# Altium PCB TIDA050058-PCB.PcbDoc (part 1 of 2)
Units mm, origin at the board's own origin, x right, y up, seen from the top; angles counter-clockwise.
Board outline 100 x 60.38 mm, 2 copper layers (Top Layer, Bottom Layer), stack 1.575 mm thick; 72 components, 26 nets, 132 pads, 53 vias.
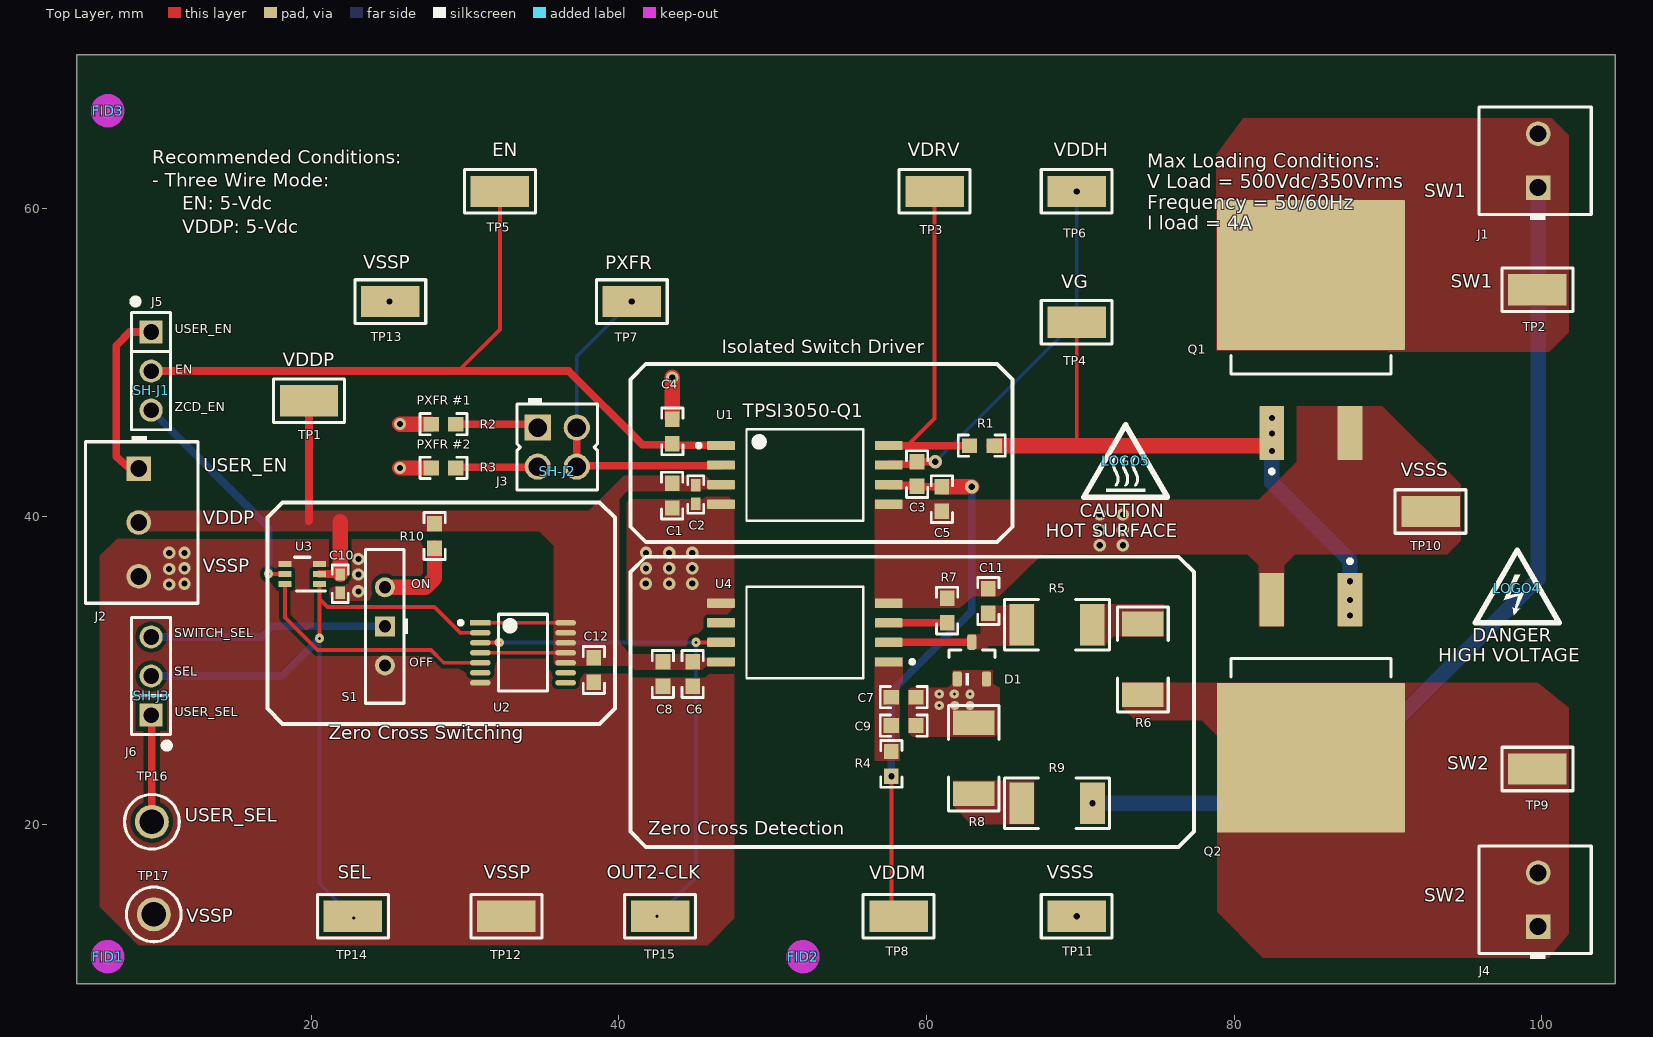
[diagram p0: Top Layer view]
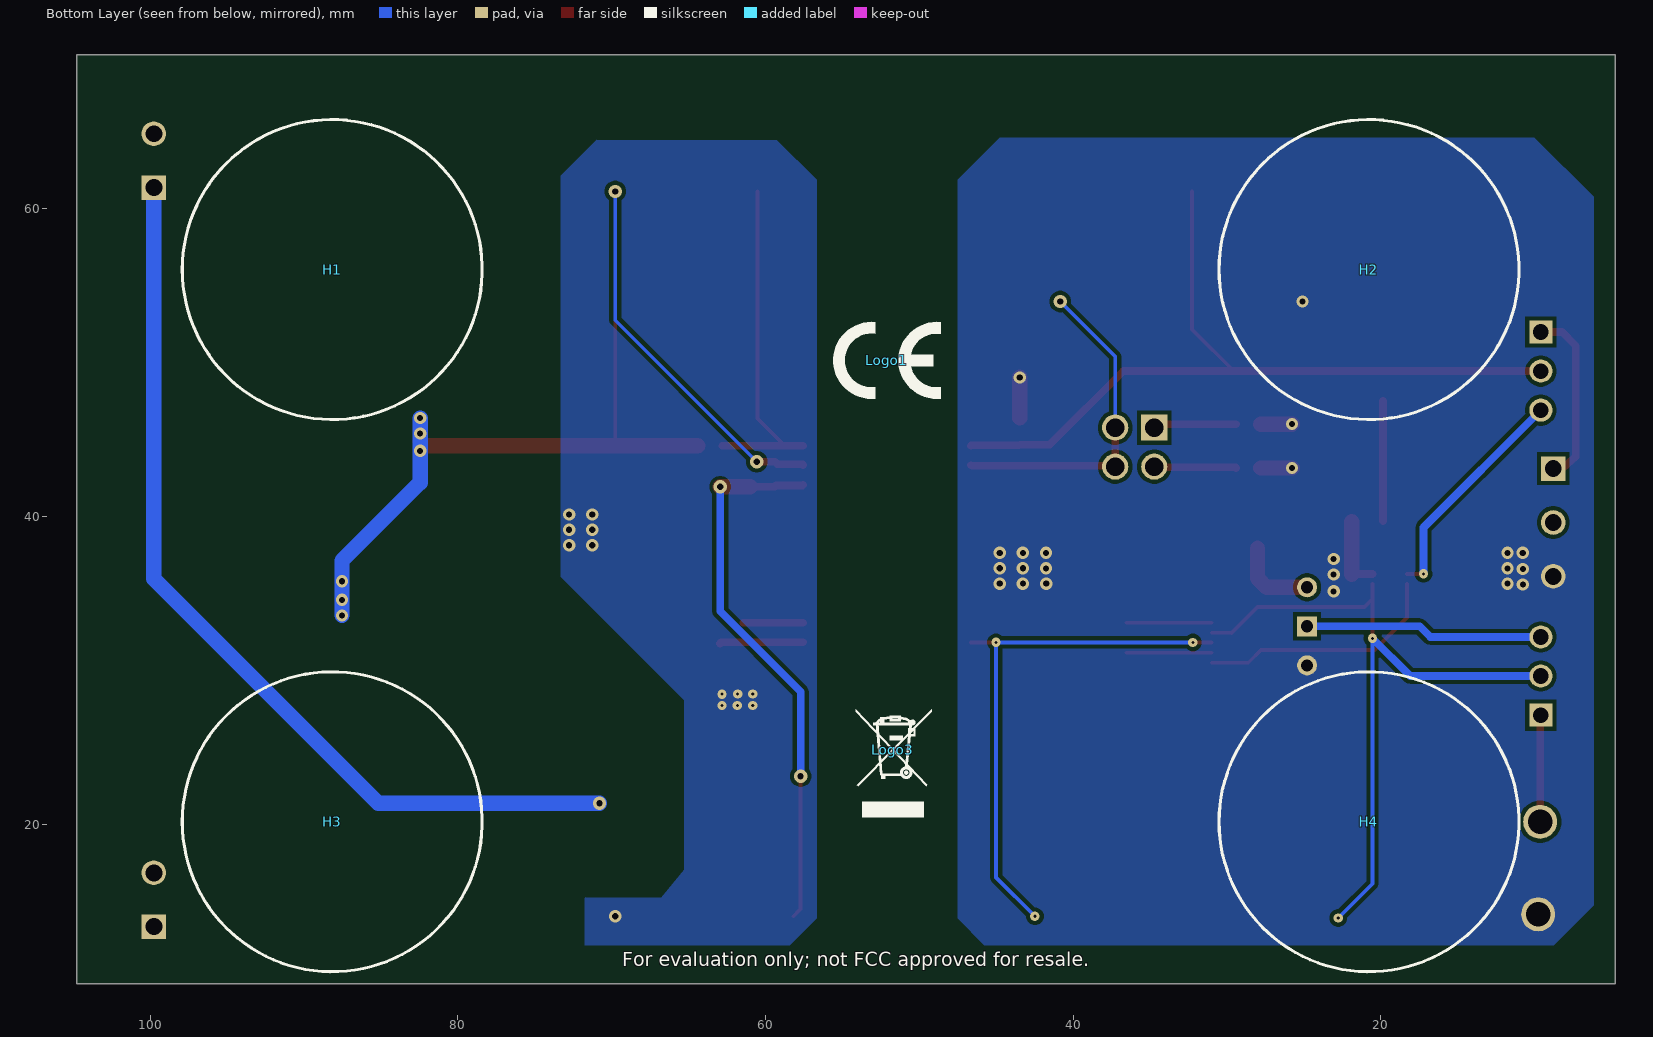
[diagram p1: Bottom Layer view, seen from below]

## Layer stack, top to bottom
Top Solder: solder mask 0.0102, Solder Resist, Dk 3.5
Top Layer: signal copper 0.0356
Dielectric1: core 1.5037, FR-4 High Tg, Dk 4.8
Bottom Layer: signal copper 0.0356
Bottom Solder: solder mask 0.0102, Solder Resist, Dk 3.5

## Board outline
4.775,9.625 104.775,9.625 104.775,70 4.775,70

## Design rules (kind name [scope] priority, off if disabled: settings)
AcuteAngle [All] p1: minimum=4.50000000000000E+0001 checktracksonly=FALSE
AssemblyTestPointUsage [All] p1: valid=2
BoardOutlineClearance BoardOutlineClearance_MountingHoles [OnCopper and InComponentClass('Mounting Holes')] p1: gap=1 ignorepadtopadclearanceinfootprint=FALSE
BoardOutlineClearance BoardOutlineClearance_Poly [OnCopper and IsPoly] p2: gap=0.635 ignorepadtopadclearanceinfootprint=FALSE
BoardOutlineClearance [OnCopper and Not InComponentClass('Logo') and not InComponentClass('FiducialMark') and not InRegion(1000,500,4000,800) and not InPoly] p3: gap=1.016 ignorepadtopadclearanceinfootprint=FALSE
Clearance Clearance_Keepouts [((IsTrack Or IsArc) And Not InPoly) And IsFree and IsKeepOut vs ((IsTrack Or IsArc) And Not InPoly) And IsFree and IsKeepOut] p1: gap=0 ignorepadtopadclearanceinfootprint=FALSE
Clearance Clearance_Poly [InPolygon] p2: gap=0.254 ignorepadtopadclearanceinfootprint=TRUE except(0.5: Fill-Fill Fill-Poly Fill-Region Poly-Poly Poly-Region Region-Region)
Clearance Clearance_FiducialMark [IsKeepOut and InComponentClass('FiducialMark') vs IsPad and InComponentClass('FiducialMark')] p3: gap=0 ignorepadtopadclearanceinfootprint=FALSE
Clearance [All] p4: gap=0.2 ignorepadtopadclearanceinfootprint=TRUE
ComponentClearance ComponentClearance_MountingHoles_FiducialMarks [InComponentClass('Mounting Holes') vs InComponentClass('FiducialMark')] p1: gap=1.27 collisioncheckmode=3 verticalgap=0.254 showdistances=FALSE
ComponentClearance ComponentClearance_Shunt [InComponentClass('Header') vs InComponentClass('Shunt')] p2: gap=0 collisioncheckmode=3 verticalgap=0 showdistances=FALSE
ComponentClearance ComponentClearance_Logo [InComponentClass('Logo')] p3: gap=0.762 collisioncheckmode=3 verticalgap=0.254 showdistances=FALSE
ComponentClearance ComponentClearance_ScrewToNut [(HasFootprint('NY PMS 440 0025 PH')) vs (HasFootprint('Keystone_1902C'))] p4: gap=0.127 collisioncheckmode=3 verticalgap=0.254 showdistances=FALSE
ComponentClearance ComponentClearance_MountingHoles [InComponentClass('Mounting Holes')] p5: gap=2.54 collisioncheckmode=3 verticalgap=2540 showdistances=FALSE
ComponentClearance ComponentClearance_SmallPassives [HasFootprint('0201*') or HasFootprint('0402*') or HasFootprint('0508') or HasFootprint('0603*') or HasFootprint('0612') or HasFootprint('0805*') or HasFootprint('0815*') or HasFootprint('0830*') or HasFootprint('1206*') or HasFootprint('1210*') or HasFootprint('1808*') or HasFootprint('1812*') or HasFootprint('1825*') or HasFootprint('2010*') or HasFootprint('2220*') or HasFootprint('2225*') or HasFootprint('2512*') or HasFootprint('2728*') or HasFootprint('3518*') vs HasFootprint('0201*') or HasFootprint('0402*') or HasFootprint('0508') or HasFootprint('0603*') or HasFootprint('0612') or HasFootprint('0805*') or HasFootprint('0815*') or HasFootprint('0830*') or HasFootprint('1206*') or HasFootprint('1210*') or HasFootprint('1808*') or HasFootprint('1812*') or HasFootprint('1825*') or HasFootprint('2010*') or HasFootprint('2220*') or HasFootprint('2225*') or HasFootprint('2512*') or HasFootprint('2728*') or HasFootprint('3518*')] p6: gap=0.38 collisioncheckmode=3 verticalgap=0.254 showdistances=FALSE
ComponentClearance ComponentClearance_THtoSMT [IsThruComponent vs IsSMTComponent] p7: gap=0.762 collisioncheckmode=3 verticalgap=0.762 showdistances=FALSE
ComponentClearance ComponentClearance_THtoTH [IsThruComponent vs IsThruComponent] p8: gap=0.508 collisioncheckmode=3 verticalgap=0.762 showdistances=FALSE
ComponentClearance [All] p9: gap=0.508 collisioncheckmode=3 verticalgap=0.254 showdistances=FALSE
DiffPairsRouting [All] p1: maxlimit=2.54 minlimit=0.254 mostfreqgap=0.254 toplayer_minwidth=0.381 toplayer_maxwidth=0.381 toplayer_prefwidth=0.381 bottomlayer_minwidth=0.381 bottomlayer_maxwidth=0.381 bottomlayer_prefwidth=0.381 maxuncoupledlength=25.4
FabricationTestPointUsage TestPointUsage [All] p1: valid=2 allowmultiple=FALSE
FabricationTestpoint Testpoint [All] p1: side=3 testpointundercomponent=TRUE minsize=1.016 maxsize=2.54 preferedsize=1.524 minholesize=0 maxholesize=1.016 preferedholesize=0.813 testpointgrid=0.025 allowsidetop=TRUE allowsidebottom=TRUE usegrid=TRUE gridtolerance=0
FanoutControl Fanout_LCC [IsLCC] p1: bgadir=Out bgaviamode=Centered fanoutstyle=Auto fanoutdirection=Alternating viagrid=0.025 // Fanout_LCC (Default Rule)
FanoutControl Fanout_BGA [IsBGA] p2: bgadir=Out bgaviamode=Centered fanoutstyle=Auto fanoutdirection=Alternating viagrid=0.025 // Fanout_BGA (Default Rule)
FanoutControl Fanout_Default [All] p4: bgadir=Out bgaviamode=Centered fanoutstyle=Auto fanoutdirection=Alternating viagrid=0.025 // Fanout_Default (Default Rule)
FanoutControl Fanout_Small [(CompPinCount < 5)] p5: bgadir=Out bgaviamode=Centered fanoutstyle=Auto fanoutdirection=OutThenIn viagrid=0.025 // Fanout_Small (Default Rule)
HoleSize [All] p1: absolutevalues=TRUE maxlimit=6.375 minlimit=0.2 maxpercent=80.000 minpercent=20.000
MinimumAnnularRing MinimumAnnularRing_ThermalPadVias [IsVia and InAnyComponent] p1: minimumring=0.15
MinimumAnnularRing [All] p2: minimumring=0.2
MinimumSolderMaskSliver MinimumSolderMaskSliver_Logo [InComponentClass('Logo') vs InComponentClass('Logo')] p1: minsoldermaskwidth=0.018
MinimumSolderMaskSliver [All] p2: minsoldermaskwidth=0.1
PlaneClearance [All] p1: clearance=0.5
PlaneConnect [All] p1: planeconnectstyle=Direct reliefexpansion=0.254 reliefentries=4 reliefconductorwidth=0.254 reliefairgap=0.254
PolygonConnect [All] p1: connectstyle=Direct reliefconductorwidth=0.254 reliefentries=4 polygonreliefangle="90 Angle" airgapwidth=0.254
RoutingVias ThermalPadVias [IsVia and InAnyComponent] p1: holewidth=0.4 width=0.8 viastyle="Through Hole" minholewidth=0.2 minwidth=0.5 maxholewidth=1 maxwidth=1.6
RoutingVias [All] p2: holewidth=0.406 width=0.864 viastyle="Through Hole" minholewidth=0.2 minwidth=0.61 maxholewidth=1.016 maxwidth=1.651
SilkToBoardRegionClearance [Not ((IsComment or IsDesignator) And (Hide <> 'False')) and not InRegion(1000,500,4000,800)] p1:
SilkToSilkClearance SilkToSilkClearance_Pb-FreeLogo [(HasFootprint('Pb-Free_Overlay_Medium') OR HasFootprint('Pb-Free_Overlay_Small')) vs (HasFootprint('Pb-Free_Overlay_Medium') OR HasFootprint('Pb-Free_Overlay_Small'))] p1: silktosilkclearance=0
SilkToSilkClearance [All] p2: silktosilkclearance=0.1
SilkToSolderMaskClearance SilkToComponentPadClearance [(IsPad or IsFill or IsRegion) and InAnycomponent] p1: minsilkscreentomaskgap=0.127 clearancetoexposedcopper=TRUE
SilkToSolderMaskClearance "Silk to Solder Mask Opening" [All] p2: minsilkscreentomaskgap=0.1 clearancetoexposedcopper=FALSE
SolderMaskExpansion [All] p1: expansion=0.05 istentingtop=FALSE
UnRoutedNet [All] p1: checkbadconnections=TRUE
Width [All] p1: maxlimit=1 minlimit=0.25 preferedwidth=0.5 minimp=50.000000 maximp=50.000000 favimp=50.000000 checkconnectedcopper=TRUE
13 further rules are at their usual default settings.

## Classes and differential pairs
component class Shunt: SH-J1 SH-J2 SH-J3
component class Header: J3 J5 J6
component class TIDA050058-Hardware: FID1 FID2 FID3 H1 H2 H3 H4 Logo1 Logo2 LOGO4 ZZ1 ZZ2 ZZ3 ZZ4
component class FiducialMark: FID1 FID2 FID3
component class AssemblyNote: ZZ1 ZZ2 ZZ3 ZZ4

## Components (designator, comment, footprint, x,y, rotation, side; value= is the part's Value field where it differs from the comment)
C1 "GRM188R71E224KA88D" 0603 43.476,41.345 r270 top value=0.22uF
C2 "GRM155R71E104KE14D" 0402 45.001,41.42 r270 top value=0.1uF
C3 "UMK107AB7105KA-T" 0603 59.391,42.745 r270 top value=1uF
C4 "C0603C102J5RACAUTO" 0603 43.49,45.52 r90 top value=1000pF
C5 "UMK107AB7105KA-T" 0603 61.007,41.12 r270 top value=1uF
C6 "GCM188R71E104KA57D" 0603 44.8,29.75 r270 top value=0.1uF
C7 "GCM188R71E104KA57D" 0603 58.525,28.25 r180 top value=0.1uF
C8 "GCM188R71E105KA64D" 0603 42.875,29.75 r270 top value=1uF
C9 "GCM188R71E105KA64D" 0603 58.525,26.4 r180 top value=1uF
C10 "CGA2B3X7R1H103K050BB" 0402 21.895,35.625 r270 top value=0.01uF
C11 "0603ZC100KAT2A" 0603 64.025,34.5 r90 top value=10pF
C12 "GCM188R71E104KA57D" 0603 38.378,30.01 r270 top value=0.1uF
D1 "BAT54S-E3-08" SOT-23 62.957,30.625 r90 top value=30V
FID1 "Fiducial" Fiducial10-20 6.775,11.375 r0 top
FID2 "Fiducial" Fiducial10-20 51.975,11.375 r0 top
FID3 "Fiducial" Fiducial10-20 6.775,66.367 r0 top
H1 "SJ-5017 (BLACK)" 3M_SJ-5017BLACK 88.175,56.045 r180 bottom
H2 "SJ-5017 (BLACK)" 3M_SJ-5017BLACK 20.775,56.045 r180 bottom
H3 "SJ-5017 (BLACK)" 3M_SJ-5017BLACK 88.175,20.145 r180 bottom
H4 "SJ-5017 (BLACK)" 3M_SJ-5017BLACK 20.775,20.145 r180 bottom
J1 "0393570002" MOLEX_39357-0002 99.775,63.125 r90 top
J2 "0393570003" MOLEX_39357-0003 8.798,39.599 r270 top
J3 "PBC02DAAN" Sullins_PxC02DAAN 36.004,44.503 r0 top
J4 "0393570002" MOLEX_39357-0002 99.775,15.075 r90 top
J5 "PEC03SAAN" CONN_PEC03SAAN 9.601,49.445 r270 top
J6 "PEC03SAAN" CONN_PEC03SAAN 9.601,29.62 r90 top
Logo1 "CE Mark" CE_Mark_5mm 52.113,50.138 r180 bottom
Logo2 "FCC disclaimer" FCC_disclaimer 44.509,90 r180 bottom
Logo3 "WEEE logo" WEEE_Minimum 51.726,24.82 r180 bottom
LOGO4 "DANGER HIGH VOLTAGE" IEC_HighVoltage_Small 98.415,35.325 r0 top
LOGO5 "CAUTION HOT SURFACE" IEC_HotSurface_Small 72.95,43.609 r0 top
Q1 "STB43N65M5" FP-STB43N65M5_D2PAK-MFG 85,53.92 r0 top
Q2 "STB43N65M5" FP-STB43N65M5_D2PAK-MFG 85,26.079 r180 top
R1 "ERJ-3GEY0R00V" 0603 63.601,44.6 r0 top value=0
R2 "CRCW06037K32FKEA" 0603 28.612,45.995 r0 top value=7.32k
R3 "CRCW060320K0FKEA" 0603 28.612,43.145 r0 top value=20.0k
R4 "CRCW060310R0JNEA" 0603 57.725,23.912 r270 top value=10
R5 "CRCW2010121KFKEF" 2010 68.491,32.95 r0 top value=121k
R6 "CRCW2010121KFKEF" 2010 74.075,30.7 r270 top value=121k
R7 "RC0603JR-070RL" 0603 61.35,33.875 r270 top value=0
R8 "CRCW2010121KFKEF" 2010 63.082,24.275 r270 top value=121k
R9 "CRCW2010121KFKEF" 2010 68.5,21.35 r0 top value=121k
R10 "CRCW060310K0JNEA" 0603 28.025,38.725 r270 top value=10k
S1 "09.03201.02" SW_09_03201_02 24.8,32.85 r270 top
SH-J1 "SNT-100-BK-G" SNT-100-BK-G 9.625,48.195 r90 top value=1x2
SH-J2 "SNT-100-BK-G" SNT-100-BK-G 36,42.925 r180 top value=1x2
SH-J3 "SNT-100-BK-G" SNT-100-BK-G 9.601,28.35 r90 top value=1x2
TP1 "5019" Keystone_5019 19.864,47.516 r180 top
TP2 "5019" Keystone_5019 99.725,54.725 r180 top
TP3 "5019" Keystone_5019 60.532,61.125 r180 top
TP4 "5019" Keystone_5019 69.775,52.625 r180 top
TP5 "5019" Keystone_5019 32.275,61.125 r0 top
TP6 "5019" Keystone_5019 69.775,61.125 r0 top
TP7 "5019" Keystone_5019 40.847,53.966 r180 top
TP8 "5019" Keystone_5019 58.194,14 r0 top
TP9 "5019" Keystone_5019 99.725,23.575 r180 top
TP10 "5019" Keystone_5019 92.777,40.316 r180 top
TP11 "5019" Keystone_5019 69.775,14 r0 top
TP12 "5019" Keystone_5019 32.694,14 r0 top
TP13 "5019" Keystone_5019 25.151,53.966 r180 top
TP14 "5019" Keystone_5019 22.719,14 r0 top
TP15 "5019" Keystone_5019 42.694,14 r180 top
TP16 "5010" Keystone5013 9.651,20.145 r90 top
TP17 "5012" Keystone5012 9.775,14.125 r90 top
U1 "TPSI3050QDWZRQ1" DWZ0008A-MFG 52.101,42.695 r0 top
U2 "SN74HCS72PWR" FP-PW0014A-IPC_C 33.775,31.134 r0 top
U3 "TMUX1219DCKR" DCK0006A_N 19.425,36.25 r180 top
U4 "AMC23C10DWVR" DWV0008A-MFG 52.101,32.445 r180 top
ZZ1 "This Assembly Note is for PCB labels only" AssemblyNoteLabel 134.974,86.15 r0 top
ZZ2 "These assemblies are ESD sensitive, ESD precautions shall be observed." AssemblyNote 134.974,83.384 r0 top
ZZ3 "These assemblies must be clean and free from flux and all contaminants. Use of no clean flux is not acceptable." AssemblyNote 134.974,81.135 r0 top
ZZ4 "These assemblies must comply with workmanship standards IPC-A-610 Class 2, unless otherwise specified." AssemblyNote 134.974,78.886 r0 top

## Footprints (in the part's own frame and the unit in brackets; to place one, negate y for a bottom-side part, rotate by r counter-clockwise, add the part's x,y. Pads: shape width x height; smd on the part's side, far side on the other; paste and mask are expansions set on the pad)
3M_SJ-5017BLACK [mm] "Bumpon, Cylindrical, 0.75 X 0.38 inch, Black"
  silkscreen extent -9.75,-9.75 9.75,9.75, body extent -9.75,-9.75 9.75,9.75, height 10.1
0402 [mm] "0402 from SM-752 data"
  rect 0.8x0.6 smd: 1(-0.6,0) 2(0.6,0)
  silkscreen extent -1.22,-0.52 1.22,0.52, body extent -0.55,-0.3 0.55,0.3, height 0.6
0603 [mm] "0603 from SM-752 data"
  rect 1x0.95 smd: 1(-0.8,0) 2(0.8,0)
  silkscreen extent -1.52,-0.69 1.52,0.69, body extent -0.87,-0.47 0.87,0.47, height 1
2010 [mm] "Chip Capacitor, Body 5.08x2.54mm, IPC Medium Density"
  rect 1.6x2.7 smd: 1(-2.3,0) 2(2.3,0)
  silkscreen extent -3.42,-1.65 3.42,1.65, body extent -2.73,-1.45 2.73,1.45, height 1.66
AssemblyNote [mm] "Assembly Note"
AssemblyNoteLabel [mm] "Assembly Note for PCB Labels"
CE_Mark_5mm [mm] "Minimum text height for CE Mark"
  silkscreen extent -3.5,-2.5 3.5,2.5
CONN_PEC03SAAN [mm] "SULLINS"
  rect 1.5x1.5 hole 1.016: 1(-2.54,0)
  round 1.5 hole 1.016: 2(0,0) 3(2.54,0)
  silkscreen extent -4.72,-1.27 3.81,1.27, body extent -3.84,-1.3 3.84,1.3, height 8.38
DCK0006A_N [mm] "SOT23, 6-Leads, Body 2x1.3mm, Pitch 0.65mm, Lead Span 2.1mm, IPC Medium Density"
  rrect25% 0.85x0.4 smd: 1(-1.125,0.65) 2(-1.125,0) 3(-1.125,-0.65) 4(1.125,-0.65) 5(1.125,0) 6(1.125,0.65)
  silkscreen extent -1.5,-1.09 0.51,1.09, body extent -1.14,-1 1.14,1, height 0.95
DWV0008A-MFG [mm]
  rrect17% 1.8x0.6 smd paste+0 mask+0: 1(-5.45,1.905) 2(-5.45,0.635) 3(-5.45,-0.635) 4(-5.45,-1.905) 5(5.45,-1.905) 6(5.45,-0.635) 7(5.45,0.635) 8(5.45,1.905)
  silkscreen extent -7.1,-2.98 3.8,2.98, body extent -6.45,-3.22 6.45,3.22, height 0.25
DWZ0008A-MFG [mm]
  rrect17% 1.8x0.6 smd paste+0 mask+0: 1(-5.45,1.905) 2(-5.45,0.635) 3(-5.45,-0.635) 4(-5.45,-1.905) 5(5.45,-1.905) 6(5.45,-0.635) 7(5.45,0.635) 8(5.45,1.905)
  silkscreen extent -7.02,-2.98 3.8,2.98, body extent -6.45,-3.22 6.45,3.22, height 0.25
FCC_disclaimer [mm]
Fiducial10-20 [mm]
  round 1 smd mask+0.5: 1(0,0)
  Top Layer keep-out circle w1.178: c0,0 r0.5
FP-PW0014A-IPC_C [mm]
  rect 1.355x0.341 smd paste+0 mask+0: 1(-2.775,1.95)
  rrect100% 1.355x0.341 smd paste+0 mask+0: 2(-2.775,1.3) 3(-2.775,0.65) 4(-2.775,0) 5(-2.775,-0.65) 6(-2.775,-1.3) 7(-2.775,-1.95) 8(2.775,-1.95) 9(2.775,-1.3) 10(2.775,-0.65) 11(2.775,0) 12(2.775,0.65) 13(2.775,1.3) 14(2.775,1.95)
  silkscreen extent -4.17,-2.5 1.6,2.5, body extent -3.55,-2.6 3.55,2.6, height 0.25
FP-STB43N65M5_D2PAK-MFG [mm]
  rrect6% 1.6x3.5 smd paste+0 mask+0: 1(-2.54,-8.503) 3(2.54,-8.503)
  rrect1% 12.2x9.75 smd paste+0 mask+0: 4(0,1.773)
  silkscreen extent -5.2,-11.12 5.2,-3.48, body extent -6.2,-10.35 6.2,6.75, height 0.25
IEC_HighVoltage_Small [mm]
  silkscreen extent -2.72,-2.24 2.72,2.47
IEC_HotSurface_Small [mm]
  silkscreen extent -2.72,-2.36 2.72,2.35
Keystone5012 [mil] "Keystone Multipurpose loops"
  round 87 hole 63: 1(0,0)
  silkscreen extent -70,-70 70,70, body extent -63,-63 63,62, height 319
Keystone5013 [mil] "Keystone Multipurpose loops"
  round 87 hole 63: 1(0,0)
  silkscreen extent -70,-70 70,70, body extent -63,-63 63,62, height 319
Keystone_5019 [mm] "Test Point, Miniature, SMT"
  rect 3.8x2.03 smd: 1(0,0)
  silkscreen extent -2.31,-1.42 2.31,1.42, body extent -1.9,-1.02 1.9,1.02, height 2.29
MOLEX_39357-0002 [mm] "Terminal Block, 3.5 mm, 2x1, TH"
  rect 1.6x1.6 hole 1.1: 1(-1.75,0)
  round 1.6 hole 1.1: 2(1.75,0)
  silkscreen extent -3.86,-3.45 3.5,3.84, body extent -3.55,-3.45 3.56,3.84, height 8.51
MOLEX_39357-0003 [mm] "Terminal Block, 3.5 mm, 3x1, TH"
  rect 1.6x1.6 hole 1.1: 1(-3.5,0)
  round 1.6 hole 1.1: 2(0,0) 3(3.5,0)
  silkscreen extent -5.61,-3.45 5.25,3.84, body extent -5.25,-3.45 5.16,3.84, height 8.51
SNT-100-BK-G [mil] "Samtec STEP model"
  round 1 on Mech3: 0(0,0)
  body extent -100,-50 100,50, height 344
SOT-23 [mm] "SOT23, 3-Leads, Body 2.9x1.3mm, Pitch 0.95mm, Lead Span 2.5mm, IPC Medium Density"
  rrect50% 1x0.6 smd: 1(-1.2,0.95) 2(-1.2,-0.95) 3(1.2,0)
  silkscreen extent -1.62,-1.5 0.7,1.5, body extent -1.16,-1.45 1.21,1.45, height 1
Sullins_PxC02DAAN [mm] "Header, 2.54mm, 2x2, TH"
  rect 1.7x1.7 hole 1.2: 1(-1.27,1.27)
  round 1.7 hole 1.2: 2(1.27,1.27) 3(-1.27,-1.27) 4(1.27,-1.27)
  silkscreen extent -2.61,-2.8 2.61,3.2, body extent -2.61,-2.8 2.61,2.8, height 8.58
SW_09_03201_02 [mm] "TH, 3-Leads, Body 2.5x10mm, Pitch 2.54mm"
  rect 1.3x1.3 hole 0.8: 1(0,0)
  round 1.3 hole 0.8: 2(-2.54,0) 3(2.54,0)
  silkscreen extent -5,-1.25 5,1.5, body extent -5,-1.25 5,1.25, height 6.4
WEEE_Minimum [mm] "WEEElie bin"
  silkscreen extent -2.42,-4.38 2.52,2.65

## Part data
C1: library part CMP-0007415-4, "CAP, CERM, 0.22 uF, 25 V, +/- 10%, X7R, 0603", Cap_Case=0603, Manufacturer=MuRata, Supplier Part Number 1=490-3290-1-ND, TempCo=X7R, Tolerance_%=10%, Value1=Unknown, Value2=25V, ValueDisplayed=0.22uF
C2: library part CMP-0006659-2, "CAP, CERM, 0.1 uF, 25 V, +/- 10%, X7R, 0402", Cap_Case=0402, Manufacturer=MuRata, Supplier Part Number 1=490-10698-1-ND, TempCo=X7R, Tolerance_%=10%, Value1=Unknown, Value2=25V, ValueDisplayed=0.1uF
C3 C5: library part CMP-0007508-5, "CAP, CERM, 1 uF, 50 V, +/- 10%, X7R, 0603", Cap_Case=0603, Manufacturer="Taiyo Yuden", Supplier Part Number 1=587-3247-1-ND, TempCo=X7R, Tolerance_%=10%, Value1=Unknown, Value2=50V, ValueDisplayed=1uF
C4: library part CMP-0006844-4, "CAP, CERM, 1000 pF, 50 V, +/- 5%, X7R, AEC-Q200 Grade 1, 0603", Cap_Case=0603, Manufacturer=Kemet, Supplier Part Number 1=399-12989-1-ND, TempCo=X7R, Tolerance_%=5%, Value1=Unknown, Value2=50V, ValueDisplayed=1000pF
C6 C7 C12: library part CMP-0084679-1, "CAP, CERM, 0.1 µF, 25 V,+/- 10%, X7R, AEC-Q200 Grade 1, 0603", Cap_Case=0603, Manufacturer=MuRata, TempCo=X7R, Tolerance_%=10%, Value2=25V, ValueDisplayed=0.1µF
C8 C9: library part CMP-0007139-4, "CAP, CERM, 1 uF, 25 V, +/- 10%, X7R, AEC-Q200 Grade 1, 0603", Cap_Case=0603, Manufacturer=MuRata, Supplier Part Number 1=490-10673-1-ND, TempCo=X7R, Tolerance_%=10%, Value1=Unknown, Value2=25V, ValueDisplayed=1uF
C10: library part CMP-0006324-2, "CAP, CERM, 0.01 uF, 50 V, +/- 10%, X7R, AEC-Q200 Grade 1, 0402", Cap_Case=0402, Manufacturer=TDK, Supplier Part Number 1=445-6893-1-ND, TempCo=X7R, Tolerance_%=10%, Value1="0.333065 ohm", Value2=50V, ValueDisplayed=0.1uF
C11: library part CMP-0006811-4, "CAP, CERM, 10 pF, 10 V, +/- 10%, X7R, 0603", Cap_Case=0603, Manufacturer=AVX, Supplier Part Number 1=0603ZC100KAT2A-ND, TempCo=X7R, Tolerance_%=10%, Value1=Unknown, Value2=10V, ValueDisplayed=10pF
D1: library part CMP-0028631-2, "Diode, Schottky, 30 V, 0.2 A, SOT-23", Manufacturer=Vishay-Semiconductor, Value1=0.2A, Value2=0.7V
FID1 FID2 FID3: library part CMP-0077181-1, "Fiducial mark.  There is nothing to buy or mount.", Manufacturer=N/A
H1 H2 H3 H4: library part CMP-0003997-1, "Bumpon, Cylindrical, 0.75 X 0.38 inch, Black", Manufacturer=3M, Supplier Part Number 1=SJ5017-0-ND
J1 J4: library part CMP-0055341-2, "Terminal Block, 3.5 mm, 2x1, Tin, TH", Manufacturer=Molex, Supplier Part Number 1=WM7877-ND
J2: library part CMP-0055340-2, "Terminal Block, 3.5 mm, 3x1, Tin, TH", Manufacturer=Molex, Supplier Part Number 1=WM7878-ND
J3: library part CMP-0054598-1, "Header, 2.54mm, 2x2, Gold, TH", Color=Black, Current_A=3A, Manufacturer="Sullins Connector Solutions", Supplier Part Number 1=S2011E-02-ND, Voltage_V=1.8kV
J5 J6: library part CMP-0002338-1, "Header, 100mil, 3x1, Tin, TH", Color=Black, Current_A=3A, Manufacturer="Sullins Connector Solutions", Supplier Part Number 1=S1012E-03-ND, Voltage_V=1.8kV
Logo1: library part CMP-0074844-1
Logo2: library part CMP-0074847-1, "FCC_disclaimer"
Logo3: library part CMP-0074769-1
LOGO4: library part CMP-0074835-1, "IEC 61010-1 High Voltage Warning"
LOGO5: library part CMP-0074837-1, "IEC 61010-1 Hot Surface Warning"
Q1 Q2: library part CMP-0088026-1, "MOSFET N-CH 650V 42A", Manufacturer=STMicroelectronics
R1: library part CMP-0025874-4, "RES, 0, 5%, 0.1 W, AEC-Q200 Grade 0, 0603", Manufacturer=Panasonic, Power_W=100mW, Supplier Part Number 1=P0.0GCT-ND, TempCo="600 ppm/C", Tolerance_%=5%, Value2=0.1W, Value_Code=0000, ValueDisplayed=0
R2: library part CMP-0022600-4, "RES, 7.32 k, 1%, 0.1 W, AEC-Q200 Grade 0, 0603", Manufacturer=Vishay-Dale, Power_W=100mW, Supplier Part Number 1=541-7.32KHCT-ND, TempCo="100 ppm/C", Tolerance_%=1%, Value2=0.1W, Value_Code=7k32, ValueDisplayed=7.32k
R3: library part CMP-0022204-4, "RES, 20.0 k, 1%, 0.1 W, AEC-Q200 Grade 0, 0603", Manufacturer=Vishay-Dale, Power_W=100mW, Supplier Part Number 1=541-20.0KHCT-ND, TempCo="100 ppm/C", Tolerance_%=1%, Value2=0.1W, Value_Code=20k0, ValueDisplayed=20.0k
R4: library part CMP-0025703-4, "RES, 10, 5%, 0.1 W, AEC-Q200 Grade 0, 0603", Manufacturer=Vishay-Dale, Power_W=100mW, Supplier Part Number 1=541-10GCT-ND, TempCo="200 ppm/C", Tolerance_%=5%, Value2=0.1W, Value_Code=10R0, ValueDisplayed=10
R5 R6 R8 R9: library part CMP-0016226-3, "RES, 121 k, 1%, 0.75 W, AEC-Q200 Grade 0, 2010", Manufacturer=Vishay-Dale, Power_W=750mW, Supplier Part Number 1=541-121KACCT-ND, TempCo="100 ppm/C", Tolerance_%=1%, Value2=0.75W, Value_Code=121k
R7: library part CMP-0025885-5, "RES, 0, 5%, 0.1 W, 0603", Manufacturer=Yageo, Power_W=100mW, Supplier Part Number 1=311-0.0GRCT-ND, TempCo="200 ppm/C", Tolerance_%=5%, Value2=0.1W, Value_Code=0000, ValueDisplayed=0
R10: library part CMP-0025701-4, "RES, 10 k, 5%, 0.1 W, AEC-Q200 Grade 0, 0603", Manufacturer=Vishay-Dale, Power_W=100mW, Supplier Part Number 1=541-10KGCT-ND, TempCo="200 ppm/C", Tolerance_%=5%, Value2=0.1W, Value_Code=10k0, ValueDisplayed=10k
S1: library part CMP-0002207-1, "Switch, SPDT, Slide, On-On, 2 Pos, TH", CurrentRating_mA=500A, Manufacturer="EAO Switch", Supplier Part Number 1=52F516
SH-J1 SH-J2 SH-J3: library part CMP-0003623-3, "Shunt, 100mil, Gold plated, Black", Alternate Manufacturer=3M, Alternate PartNumber=969102-0000-DA, Manufacturer=Samtec, Supplier Part Number 1=SAM8858-ND
TP1 TP2 TP3 TP4 TP5 TP6 TP7 TP8 TP9 TP10 TP11 TP12 TP13 TP14 TP15: library part CMP-0055162-1, "Test Point, Miniature, SMT", Manufacturer=Keystone, Supplier Part Number 1=36-5019TR-ND
TP16: library part CMP-0055150-1, "Test Point, Multipurpose, Orange, TH", Color=Orange, Manufacturer=Keystone, PartNumber=5013, Supplier Part Number 1=36-5013-ND
TP17: library part CMP-0055149-1, "Test Point, Multipurpose, White, TH", Color=White, Manufacturer=Keystone, Supplier Part Number 1=36-5012-ND
U1: library part CMP-0095183-1, "Automotive Reinforced Isolated Switch Driver With Integrated 10-V Gate Supply", Manufacturer="Texas Instruments", Max Supply Voltage=5.5V, Min Supply Voltage=3V, Nominal Supply Current=4-33mA, Operating Temperature Range="-40°C to +150°C", Output Voltage=10V
U2: library part CMP-04902-000014-1, "IC FF D-TYPE DUAL 2BIT 14TSSOP"
U3: library part CMP-0860319-1, "1-ch, 2:1 general-purpose analog multiplexer with 1.8-V logic control, DCK0006A (SOT-SC70-6)", Alternate Manufacturer="Texas Instruments", Operating Temperature Range="-40 to 125 C", Rating=Catalog
U4: library part CMP-0092832-2, "High-Speed Reinforced Differential Comparator w/ Reference, Open-Drain and Push-Pull Output", Manufacturer="Texas Instruments", Operating Temperature Range=to
ZZ1: library part CMP-0003616-3
ZZ2: library part CMP-0077236-1
ZZ3: library part CMP-0077237-1
ZZ4: library part CMP-0077238-1

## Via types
v1: diameter 0.8, hole 0.4, Top Layer to Bottom Layer, tented both sides, 35 vias
v2: diameter 0.61, hole 0.203, Top Layer to Bottom Layer, tented both sides, 12 vias
v3: diameter 0.864, hole 0.406, Top Layer to Bottom Layer, tented both sides, 6 vias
